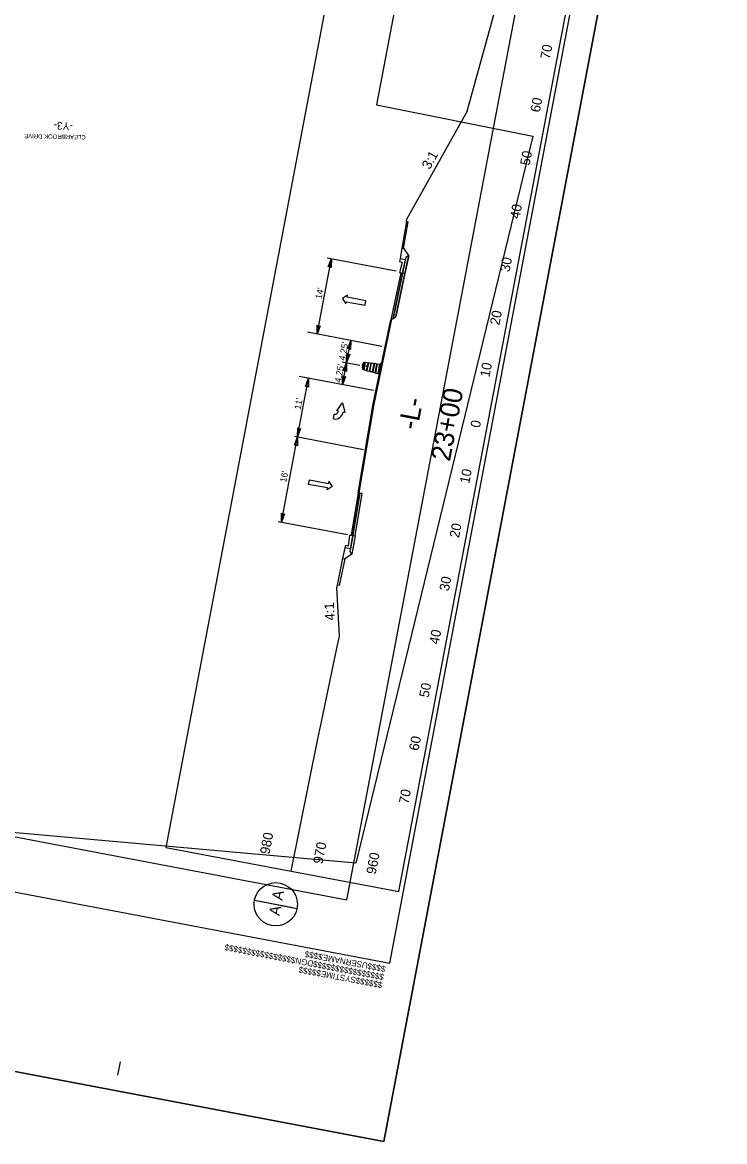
# Model space of a CAD drawing. Extents: x 1615680 to 1619687, y 899305 to 902270.
# Drawn here: x 1616427 to 1617075, y 899305 to 900338 of the extents above; entities that cross this region are included whole.
import ezdxf

# ---------------------------------------------------------------- set-up
doc = ezdxf.new("R2010")
doc.units = 0
for name, color, linetype in [('Default', 7, 'Continuous'), ('DEV CRASH CUSHION CELL', 7, 'Continuous'), ('DEV DRUM PLAN VIEW CELL', 7, 'Continuous'), ('MARK LEFT TURN ARROW CELL', 7, 'Continuous'), ('MARK RIGHT TURN ARROW CELL', 7, 'Continuous'), ('Old_Level_20', 7, 'Continuous'), ('Prop Conc 2ft 6in Curb and Gutter', 7, 'Continuous'), ('Prop Conc 4in Sidewalk', 7, 'Continuous'), ('Prop Conc Drive Radius Type', 7, 'Continuous'), ('Prop EOT', 7, 'Continuous'), ('Prop Mkg 3ft Min Skp 9ft White', 7, 'Continuous'), ('Prop Mkg Min Skp 6ft Yellow', 7, 'Continuous'), ('Prop Mkg Solid White Crosswalks', 7, 'Continuous'), ('Prop Mkg Solid White Gore Line', 7, 'Continuous'), ('Prop Mkg Solid White Lane Line', 7, 'Continuous'), ('Prop Mkg Solid White Stop Bar', 7, 'Continuous'), ('Prop Mkg Solid Yellow Diagonals', 7, 'Continuous'), ('Prop Mkg Yld Lin', 7, 'Continuous'), ('Prop Paint Stripe', 7, 'Continuous'), ('Scratch_Level_5', 7, 'Continuous'), ('Scratch_Level_6', 7, 'Continuous'), ('Scratch_Level_7', 7, 'Continuous'), ('Scratch_Level_8', 7, 'Continuous'), ('Stage 5', 7, 'Continuous'), ('TCP Linework', 7, 'Continuous')]:
    doc.layers.add(name, color=color, linetype=linetype)

msp = doc.modelspace()

# ---------------------------------------------------------------- linework, layer by layer
at = {"layer": 'Default'}
for q in [(1616680.4, 899520.2), (1616676.6, 899521)]:
    msp.add_line((1616641.1, 899527.7), q, dxfattribs=at)
for points in [[(1616709.3, 900112.5), (1616712.2, 900120.2), (1616712.1, 900111.9), (1616710.9, 900113.2)], [(1616701.9, 900058.3), (1616699, 900050.6), (1616699.1, 900058.8), (1616700.3, 900057.5)], [(1616727.3, 900036.9), (1616730.2, 900044.6), (1616730, 900036.4), (1616728.8, 900037.7)], [(1616729.1, 900031.9), (1616726.3, 900024.2), (1616726.4, 900032.5), (1616727.6, 900031.2)], [(1616723.4, 900016.5), (1616726.3, 900024.2), (1616726.2, 900015.9), (1616724.9, 900017.2)], [(1616688.3, 900002), (1616691.2, 900009.7), (1616691.1, 900001.4), (1616689.9, 900002.7)], [(1616725.3, 900011.4), (1616722.4, 900003.7), (1616722.5, 900012), (1616723.7, 900010.7)], [(1616683.8, 899963.3), (1616680.9, 899955.6), (1616681.1, 899963.9), (1616682.3, 899962.6)], [(1616678.1, 899947.9), (1616680.9, 899955.6), (1616680.8, 899947.3), (1616679.6, 899948.6)], [(1616668.9, 899884.7), (1616666, 899877), (1616666.1, 899885.3), (1616667.4, 899884)]]:
    msp.add_lwpolyline(points, close=True, dxfattribs=at)
msp.add_circle((1616660.8, 899524), 20, dxfattribs=at)
at = {"layer": 'DEV CRASH CUSHION CELL'}
for points in [[(1616837.5, 900256.5), (1616859, 900334.2), (1616864.2, 900352.4), (1616867.9, 900367.1), (1616880.1, 900409.8)], [(1616674.9, 899554.7), (1616699.8, 899676.8), (1616704.2, 899698.3), (1616717.3, 899760.6), (1616719.8, 899771.7)]]:
    msp.add_lwpolyline(points, dxfattribs=at)
at = {"layer": 'DEV DRUM PLAN VIEW CELL'}
for p, q in [((1616699, 900050.6), (1616712.2, 900120.2)), ((1616708.2, 900120.9), (1616772, 900108.8)), ((1616722.4, 900003.7), (1616730.2, 900044.6)), ((1616722.3, 900024.9), (1616738.4, 900021.9)), ((1616666, 899877), (1616691.2, 900009.7)), ((1616678.1, 899956.2), (1616741.9, 899944)), ((1616663.2, 899877.6), (1616727, 899865.4))]:
    msp.add_line(p, q, dxfattribs=at)
at = {"layer": 'MARK LEFT TURN ARROW CELL'}
for points in [[(1616775.2, 900107.3), (1616775.2, 900107.3), (1616775.2, 900107.3), (1616778, 900106.8), (1616778, 900106.8), (1616780.6, 900119), (1616775.6, 900120), (1616775.6, 900120), (1616775.2, 900117.5), (1616775.2, 900117.5), (1616775.2, 900117.5), (1616777.6, 900117.1), (1616775.2, 900107.3)], [(1616729.1, 899865), (1616729.1, 899865), (1616729.1, 899865), (1616732, 899864.5), (1616732, 899864.5), (1616729.9, 899852.2), (1616724.9, 899853.1), (1616724.9, 899853.1), (1616725.4, 899855.6), (1616725.4, 899855.6), (1616725.4, 899855.6), (1616727.9, 899855.1), (1616729.1, 899865)]]:
    msp.add_lwpolyline(points, dxfattribs=at)
at = {"layer": 'Prop Conc 4in Sidewalk'}
msp.add_lwpolyline([(1616176.3, 901060.7), (1616848.5, 900914.3), (1616896.3, 900812.9), (1616872.9, 900688.2), (1616835.9, 900695.2), (1616753.9, 900262.2), (1616898.1, 900233.4), (1616734.8, 899562.1), (1616203, 899609.4), (1616198.7, 899647.1), (1615822.7, 899825.1), (1616054.3, 901080.8)], close=True, dxfattribs=at)
at = {"layer": 'Prop Conc Drive Radius Type'}
for p, q in [((1616723.2, 900439.6), (1616559.3, 899576.6)), ((1616774.5, 899535.8), (1616938.4, 900398.7)), ((1616559.3, 899576.6), (1616774.5, 899535.8))]:
    msp.add_line(p, q, dxfattribs=at)
at = {"layer": 'Prop EOT'}
msp.add_lwpolyline([(1616737, 899904), (1616736.9, 899904), (1616750.8, 899986), (1616767.1, 900063.6)], dxfattribs=at)
at = {"layer": 'Prop Mkg 3ft Min Skp 9ft White'}
for points in [[(1616777.3, 900129.8), (1616778.9, 900129.5), (1616783.1, 900154.2), (1616781.5, 900154.5), (1616777.3, 900129.8)], [(1616722.9, 899843.3), (1616724.5, 899843.1), (1616719.4, 899818.5), (1616717.7, 899818.8), (1616722.9, 899843.3)]]:
    msp.add_lwpolyline(points, dxfattribs=at)
at = {"layer": 'Prop Mkg Solid White Crosswalks'}
msp.add_lwpolyline([(1616729.1, 899865), (1616730.4, 899864.8)], dxfattribs=at)
at = {"layer": 'Prop Mkg Solid White Gore Line'}
for points in [[(1616778, 900106.8), (1616780.1, 900106.4), (1616783.6, 900123.2), (1616781.1, 900121.5), (1616778, 900106.8)], [(1616769.2, 900065), (1616769.2, 900065), (1616769.2, 900065), (1616771.7, 900066.7), (1616771.7, 900066.7), (1616780.1, 900106.4), (1616778, 900106.8), (1616778, 900106.8), (1616769.2, 900065)], [(1616736.9, 899904), (1616737.7, 899903.8), (1616737.7, 899903.8), (1616751.6, 899985.9), (1616751.6, 899985.9), (1616768.1, 900064.3), (1616767.1, 900063.6), (1616767.1, 900063.6), (1616750.8, 899986), (1616750.8, 899986), (1616736.9, 899904), (1616736.9, 899904), (1616736.9, 899904)], [(1616738.6, 899903.6), (1616732, 899864.5), (1616732, 899864.5), (1616734.1, 899864.1), (1616740.7, 899903.3), (1616740.7, 899903.3), (1616738.6, 899903.6), (1616738.6, 899903.6), (1616738.6, 899903.6)], [(1616732, 899864.5), (1616734.1, 899864.1), (1616731.2, 899847.2), (1616729.5, 899849.7), (1616732, 899864.5)]]:
    msp.add_lwpolyline(points, dxfattribs=at)
at = {"layer": 'Prop Mkg Solid White Lane Line'}
for p, q in [((1616727, 900086.4), (1616722.4, 900083.3)), ((1616722.4, 900083.3), (1616725.6, 900078.5)), ((1616725.6, 900078.5), (1616725.9, 900080.4)), ((1616725.9, 900080.4), (1616743.3, 900077.1)), ((1616726.7, 900084.5), (1616727, 900086.4)), ((1616744.1, 900081.2), (1616726.7, 900084.5)), ((1616743.3, 900077.1), (1616744.1, 900081.2)), ((1616717.2, 899979.6), (1616722.5, 899987.1)), ((1616722.5, 899987.1), (1616724.6, 899978.2)), ((1616714, 899972.2), (1616714.8, 899976.7)), ((1616718.7, 899979.3), (1616717.2, 899979.6)), ((1616724.6, 899978.2), (1616723.1, 899978.5)), ((1616691.2, 899911.8), (1616692, 899915.9)), ((1616708.6, 899908.5), (1616691.2, 899911.8)), ((1616692, 899915.9), (1616709.4, 899912.6)), ((1616709.4, 899912.6), (1616709.8, 899914.4)), ((1616709.8, 899914.4), (1616713, 899909.8)), ((1616713, 899909.8), (1616708.3, 899906.6)), ((1616708.3, 899906.6), (1616708.6, 899908.5))]:
    msp.add_line(p, q, dxfattribs=at)
for radius in [7.8, 3.3]:
    msp.add_arc((1616715.5, 899979.9), radius, 259.2494, 349.2494, dxfattribs=at)
at = {"layer": 'Prop Mkg Solid White Stop Bar'}
for points in [[(1616837.5, 900256.5), (1616781.9, 900157), (1616781.9, 900157)], [(1616781.5, 900154.5), (1616781.9, 900157)], [(1616777.3, 900129.8), (1616777.3, 900129.8), (1616775.6, 900120)], [(1616722.9, 899843.3), (1616724.9, 899853.1), (1616724.9, 899853.1)], [(1616717.2, 899816.4), (1616717.7, 899818.8), (1616717.7, 899818.8)], [(1616719.8, 899771.7), (1616719.8, 899771.7), (1616717.2, 899816.4)]]:
    msp.add_lwpolyline(points, dxfattribs=at)
at = {"layer": 'Prop Mkg Solid Yellow Diagonals'}
for points in [[(1616783.6, 900123.2), (1616779, 900129.9)], [(1616783.6, 900123.2), (1616780.1, 900106.4), (1616780.1, 900106.4)], [(1616780.1, 900106.4), (1616771.7, 900066.7), (1616771.7, 900066.7)], [(1616734.1, 899864.1), (1616740.7, 899903.3), (1616740.7, 899903.3)], [(1616734.1, 899864.1), (1616731.2, 899847.2)], [(1616731.2, 899847.2), (1616724.4, 899842.6)]]:
    msp.add_lwpolyline(points, dxfattribs=at)
at = {"layer": 'Prop Mkg Yld Lin'}
for points in [[(1616767.2, 900063.7), (1616767.2, 900063.7), (1616767.2, 900063.7), (1616769.2, 900065), (1616769.2, 900065), (1616778, 900106.8), (1616776.4, 900107.1), (1616776.4, 900107.1), (1616767.2, 900063.7)], [(1616737, 899904), (1616730.4, 899864.8), (1616730.4, 899864.8), (1616732, 899864.5), (1616738.6, 899903.6), (1616738.6, 899903.6), (1616737, 899904), (1616737, 899904), (1616737, 899904)]]:
    msp.add_lwpolyline(points, dxfattribs=at)
at = {"layer": 'Prop Paint Stripe'}
for p, q in [((1616758.8, 900039.2), (1616690, 900052.3)), ((1616751, 899998.3), (1616682.3, 900011.3))]:
    msp.add_line(p, q, dxfattribs=at)
at = {"layer": 'Scratch_Level_5'}
for p, q in [((1616742.1, 900018), (1616741.4, 900018.1)), ((1616741.5, 900019.7), (1616741.5, 900019.7)), ((1616742.1, 900022.8), (1616742, 900022.8)), ((1616742.1, 900018), (1616743.3, 900024.1)), ((1616742.4, 900017.4), (1616743.8, 900024.6)), ((1616742.4, 900017.4), (1616744.7, 900016.9)), ((1616743.3, 900024.1), (1616742.6, 900024.3)), ((1616743.8, 900024.6), (1616746.1, 900024.1)), ((1616744.7, 900016.9), (1616746.1, 900024.1)), ((1616744.7, 900016.9), (1616745.1, 900016.7)), ((1616745.1, 900016.7), (1616746.5, 900024.2)), ((1616745.1, 900016.7), (1616747.4, 900016.3)), ((1616746.1, 900024.1), (1616746.5, 900024.2)), ((1616746.5, 900024.2), (1616748.8, 900023.8)), ((1616747.4, 900016.3), (1616748.8, 900023.8)), ((1616747.4, 900016.3), (1616747.8, 900016)), ((1616747.8, 900016), (1616749.3, 900023.9)), ((1616747.8, 900016), (1616750.1, 900015.6)), ((1616748.8, 900023.8), (1616749.3, 900023.9)), ((1616749.3, 900023.9), (1616751.6, 900023.5)), ((1616750.1, 900015.6), (1616751.6, 900023.5)), ((1616750.1, 900015.6), (1616750.4, 900015.3)), ((1616750.4, 900015.3), (1616752, 900023.6)), ((1616750.4, 900015.3), (1616752.7, 900014.9)), ((1616751.6, 900023.5), (1616752, 900023.6)), ((1616752, 900023.6), (1616754.3, 900023.1)), ((1616752.7, 900014.9), (1616754.3, 900023.1)), ((1616753.1, 900014.6), (1616754.7, 900023.2)), ((1616754.3, 900023.1), (1616754.7, 900023.2)), ((1616754.7, 900023.2), (1616757, 900022.8)), ((1616755.4, 900014.2), (1616757, 900022.8)), ((1616755.7, 900013.9), (1616757.4, 900022.9)), ((1616756.4, 900013.4), (1616758.3, 900023.2)), ((1616757, 900022.8), (1616757.4, 900022.9)), ((1616758.3, 900023.2), (1616757.9, 900023.3)), ((1616752.7, 900014.9), (1616753.1, 900014.6)), ((1616753.1, 900014.6), (1616755.4, 900014.2)), ((1616755.4, 900014.2), (1616755.7, 900013.9)), ((1616756.4, 900013.4), (1616756, 900013.4))]:
    msp.add_line(p, q, dxfattribs=at)
for points in [[(1616745.1, 900016.7), (1616745.8, 900020.5), (1616742, 900021.2), (1616741.9, 900021), (1616741.9, 900020.9), (1616741.9, 900020.7), (1616741.9, 900020.6), (1616741.8, 900020.4), (1616741.8, 900020.2), (1616741.8, 900020), (1616741.8, 900019.9), (1616741.8, 900019.8), (1616741.8, 900019.8), (1616741.7, 900019.7), (1616741.6, 900019.7), (1616741.6, 900019.7), (1616741.5, 900019.7), (1616741.4, 900019.7), (1616741.4, 900019.7), (1616741.3, 900019.8), (1616741.3, 900019.8), (1616741.2, 900019.9), (1616741.2, 900020), (1616741.2, 900020.1), (1616741.3, 900020.3), (1616741.3, 900020.7), (1616741.3, 900021), (1616741.4, 900021.2), (1616741.4, 900021.3), (1616740.9, 900021.4), (1616740.9, 900021.2), (1616740.8, 900020.9), (1616740.8, 900020.7), (1616740.8, 900020.4), (1616740.8, 900020.1), (1616740.7, 900019.8), (1616740.7, 900019.5), (1616740.8, 900019.3), (1616740.8, 900018.9), (1616740.8, 900018.8), (1616740.8, 900018.7), (1616740.8, 900018.6), (1616740.9, 900018.5), (1616741, 900018.4), (1616741, 900018.3), (1616741.1, 900018.2), (1616741.2, 900018.2), (1616741.3, 900018.1), (1616741.4, 900018.1), (1616742.1, 900018), (1616742.2, 900017.9), (1616742.2, 900017.8), (1616742.2, 900017.7), (1616742.3, 900017.6), (1616742.3, 900017.5), (1616742.4, 900017.4), (1616744.7, 900016.9)], [(1616746.5, 900024.2), (1616745.8, 900020.5), (1616742, 900021.2), (1616742, 900021.5), (1616742.1, 900021.7), (1616742.1, 900021.9), (1616742.2, 900022.1), (1616742.2, 900022.3), (1616742.3, 900022.4), (1616742.3, 900022.5), (1616742.3, 900022.5), (1616742.3, 900022.6), (1616742.2, 900022.7), (1616742.2, 900022.7), (1616742.1, 900022.8), (1616742, 900022.8), (1616742, 900022.8), (1616741.9, 900022.8), (1616741.8, 900022.7), (1616741.8, 900022.7), (1616741.8, 900022.6), (1616741.7, 900022.6), (1616741.7, 900022.5), (1616741.7, 900022.3), (1616741.6, 900022.2), (1616741.6, 900022.1), (1616741.5, 900021.9), (1616741.5, 900021.7), (1616741.4, 900021.6), (1616741.4, 900021.5), (1616741.4, 900021.3), (1616740.9, 900021.4), (1616740.9, 900021.6), (1616741, 900021.8), (1616741, 900022), (1616741.1, 900022.2), (1616741.2, 900022.4), (1616741.2, 900022.6), (1616741.3, 900022.8), (1616741.4, 900023.1), (1616741.5, 900023.3), (1616741.6, 900023.6), (1616741.7, 900023.8), (1616741.8, 900023.9), (1616741.8, 900023.9), (1616741.9, 900024), (1616742, 900024.1), (1616742, 900024.1), (1616742.1, 900024.2), (1616742.2, 900024.2), (1616742.3, 900024.3), (1616742.4, 900024.3), (1616742.5, 900024.3), (1616742.6, 900024.3), (1616742.6, 900024.3), (1616743.3, 900024.1), (1616743.4, 900024.3), (1616743.5, 900024.3), (1616743.5, 900024.4), (1616743.6, 900024.5), (1616743.7, 900024.5), (1616743.8, 900024.6), (1616743.8, 900024.6), (1616746.1, 900024.1)], [(1616747.4, 900016.3), (1616748.8, 900023.8), (1616749.3, 900023.9), (1616751.6, 900023.5), (1616752, 900023.6), (1616750.4, 900015.3), (1616750.1, 900015.6), (1616747.8, 900016)], [(1616752.7, 900014.9), (1616754.3, 900023.1), (1616754.7, 900023.2), (1616757, 900022.8), (1616757.4, 900022.9), (1616757.5, 900023), (1616757.5, 900023), (1616757.5, 900023.1), (1616757.6, 900023.2), (1616757.6, 900023.2), (1616757.7, 900023.2), (1616757.8, 900023.3), (1616757.8, 900023.3), (1616757.9, 900023.3), (1616757.9, 900023.3), (1616758.3, 900023.2), (1616756.4, 900013.4), (1616756, 900013.4), (1616756, 900013.5), (1616755.9, 900013.5), (1616755.9, 900013.5), (1616755.8, 900013.6), (1616755.8, 900013.6), (1616755.8, 900013.7), (1616755.7, 900013.7), (1616755.7, 900013.8), (1616755.7, 900013.8), (1616755.7, 900013.9), (1616755.7, 900013.9), (1616755.4, 900014.2), (1616753.1, 900014.6)]]:
    msp.add_lwpolyline(points, close=True, dxfattribs=at)
for centre, radius, start, end in [((1616749.6, 900019.7), 8.85, 152.3001, 186.1986), ((1616741.6, 900018.9), 0.783, 186.1986, 259.2494), ((1616750.1, 900019.7), 8.85, 160.5754, 177.9234), ((1616741.5, 900020), 0.274, 177.9234, 259.2494), ((1616741.5, 900020), 0.274, 259.2494, 357.3981), ((1616742, 900022.5), 0.274, 79.2494, 160.5754), ((1616742.5, 900023.5), 0.783, 79.2494, 152.3001), ((1616750.7, 900019.5), 8.85, 161.1006, 177.3981), ((1616742, 900022.5), 0.274, 341.1006, 79.2494), ((1616743.5, 900018.2), 1.35, 191.5554, 219.7629), ((1616744.5, 900023.4), 1.35, 118.7358, 146.9434), ((1616757.8, 900022.9), 0.392, 79.2494, 169.2494), ((1616756.1, 900013.8), 0.392, 169.2494, 259.2494)]:
    msp.add_arc(centre, radius, start, end, dxfattribs=at)
at = {"layer": 'Scratch_Level_6'}
msp.add_lwpolyline([(1616775.2, 900107.3), (1616776.4, 900107.1)], dxfattribs=at)
at = {"layer": 'Scratch_Level_7'}
for p, q in [((1616766.3, 899469.7), (1616766.3, 899469.7)), ((1616515.1, 899366.2), (1616517.4, 899378.5))]:
    msp.add_line(p, q, dxfattribs=at)
msp.add_lwpolyline([(1616014.5, 901139.2), (1615734.7, 899665.5), (1616766.3, 899469.7), (1617046.1, 900943.3)], close=True, dxfattribs=at)
at = {"layer": 'Scratch_Level_8'}
msp.add_lwpolyline([(1616054.3, 901080.8), (1615793.2, 899705.3), (1616726.5, 899528.1), (1616890.5, 900391.5), (1616774.3, 900413.6), (1616871.5, 900925.6)], close=True, dxfattribs=at)
at = {"layer": 'Stage 5'}
for points in [[(1616760.5, 899304.9), (1615679.8, 899510.1), (1615994.7, 901168.4), (1617075.3, 900963.2)], [(1616760.5, 899304.9), (1617075.3, 900963.2), (1615994.7, 901168.4), (1615679.8, 899510.1)]]:
    msp.add_lwpolyline(points, close=True, dxfattribs=at)

# ---------------------------------------------------------------- texts
at = {"layer": 'Default'}
for s, height, rotation, p in [('CLEARBROOK DRIVE', 4, 178.7509, (1616485.3, 900234.2)), ("14'", 6, 79.2493, (1616703.2, 900082.5)), ("4.25'", 6, 79.2493, (1616724.8, 900025.7)), ("4.25'", 6, 79.2493, (1616720.9, 900005.3)), ("11'", 6, 79.2493, (1616683.8, 899980.5)), ("16'", 6, 79.2493, (1616670.5, 899913.2)), ('A', 10, 79.2531, (1616666.8, 899527.1)), ('A', 10, 79.2531, (1616664.2, 899513))]:
    msp.add_text(s, height=height, rotation=rotation, dxfattribs=at).set_placement(p)
at = {"layer": 'MARK RIGHT TURN ARROW CELL'}
for s, rotation, p in [('3:1', 60.8161, (1616803, 900201.9)), ('4:1', 93.2856, (1616715.4, 899786.3))]:
    msp.add_text(s, height=9, rotation=rotation, dxfattribs=at).set_placement(p)
at = {"layer": 'Old_Level_20'}
for s, p in [('70', (1616913.9, 900303.9)), ('60', (1616904.6, 900254.8)), ('50', (1616895.2, 900205.7)), ('40', (1616885.9, 900156.5)), ('30', (1616876.6, 900107.4)), ('20', (1616867.3, 900058.3)), ('10', (1616858.1, 900010.2)), ('0', (1616849.3, 899963.5)), ('10', (1616839.5, 899912)), ('20', (1616830, 899861.8)), ('30', (1616820.6, 899812.7)), ('40', (1616811.3, 899763.6)), ('50', (1616802, 899714.4)), ('60', (1616792.6, 899665.3)), ('70', (1616783.3, 899616.2))]:
    msp.add_text(s, height=9, rotation=79.2494, dxfattribs=at).set_placement(p)
at = {"layer": 'Prop Conc 2ft 6in Curb and Gutter'}
msp.add_text('-Y3-', height=7, rotation=178.0747, dxfattribs=at).set_placement((1616473.5, 900245.9))
at = {"layer": 'Prop Mkg Min Skp 6ft Yellow'}
for s, p in [('23+00', (1616821.6, 899932.3)), ('-L-', (1616791.6, 899961.3))]:
    msp.add_text(s, height=18, rotation=79.2494, dxfattribs=at).set_placement(p)
at = {"layer": 'Prop Mkg Solid White Crosswalks'}
for p in [(1616781.5, 900154.5), (1616777.3, 900129.8), (1616777.6, 900117.1), (1616775.2, 900107.3), (1616775.2, 900107.3), (1616729.1, 899865), (1616729.1, 899865), (1616727.9, 899855.1), (1616722.9, 899843.3), (1616717.7, 899818.8)]:
    msp.add_text('X', height=0.00125, rotation=79.2494, dxfattribs=at).set_placement(p)
at = {"layer": 'Scratch_Level_7'}
for s, p in [('$$$$$$$$$$$$$$$$DGN$$$$$$$$$$$$$$$$', (1616761.2, 899459.3)), ('$$$$USERNAME$$$$', (1616762.6, 899466.8)), ('$$$$$$SYSTIME$$$$$', (1616759.8, 899451.9))]:
    msp.add_text(s, height=5.584, rotation=169.2494, dxfattribs=at).set_placement(p)
at = {"layer": 'TCP Linework'}
for s, p in [('980', (1616654.9, 899569.7)), ('970', (1616704, 899560.8)), ('960', (1616753.1, 899551.2))]:
    msp.add_text(s, height=9, rotation=79.2494, dxfattribs=at).set_placement(p)

doc.saveas('drawing.dxf')
